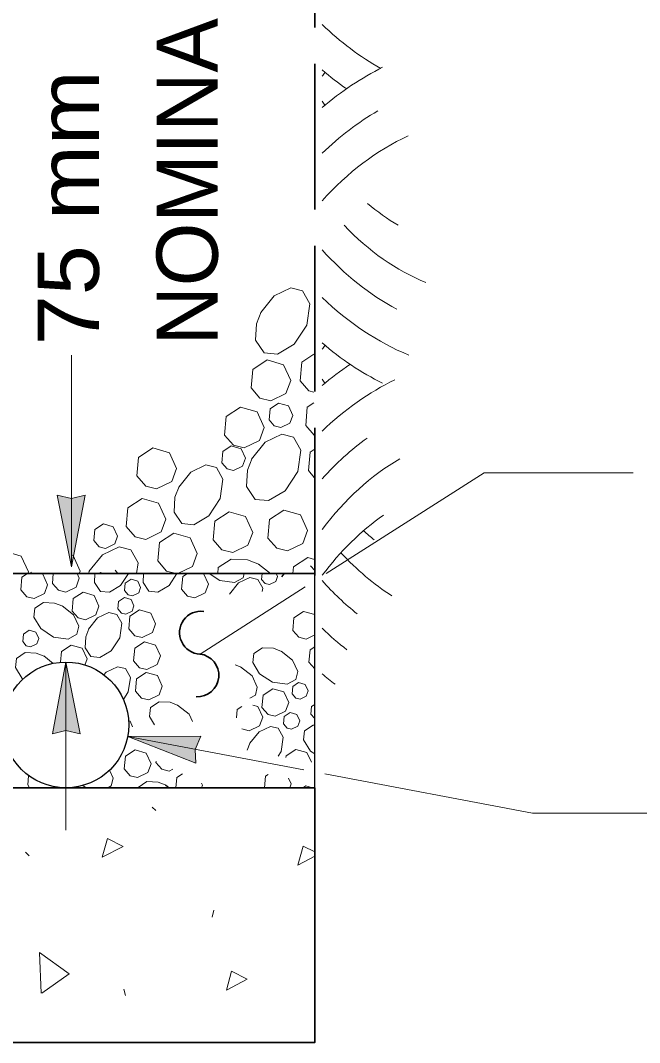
# Model space of a CAD drawing. Extents: x 17672 to 18472, y -9785 to -9267.
# Drawn here: x 18170.6 to 18206.3, y -9679.5 to -9620.6 of the extents above; entities that cross this region are included whole.
import ezdxf

# ---------------------------------------------------------------- set-up
doc = ezdxf.new("R2010")
doc.units = 0
doc.header["$LTSCALE"] = 1.4
doc.linetypes.add('LONG_DASHED', pattern=[7.5, 6, -1.5])
for name, color, linetype, lineweight in [('1', 7, 'Continuous', 13), ('15', 7, 'Continuous', 13), ('16', 7, 'Continuous', 13)]:
    doc.layers.add(name, color=color, linetype=linetype, lineweight=lineweight)
doc.layers.add('19', color=7, linetype='Continuous')

msp = doc.modelspace()

# ---------------------------------------------------------------- hatches: boundary and pattern name
at = {"layer": '16'}
for points in [[(18173.572, -9652.079), (18174.354, -9647.942), (18173.572, -9648.128), (18172.751, -9647.942)], [(18173.246, -9657.572), (18172.465, -9661.709), (18173.246, -9661.523), (18174.067, -9661.709)], [(18176.808, -9661.873), (18180.727, -9663.413), (18180.69, -9662.609), (18181.026, -9661.839)]]:
    msp.add_hatch(color=256, dxfattribs=at).paths.add_polyline_path(points)

# ---------------------------------------------------------------- linework, layer by layer
at = {"layer": '1', "linetype": 'LONG_DASHED', "lineweight": 35}
msp.add_line((18187.59, -9652.464), (18187.59, -9595.62), dxfattribs=at)
at = {"layer": '1'}
for p, q in [((18187.553, -9644.488), (18187.068, -9643.931)), ((18187.564, -9646.918), (18187.224, -9646.526)), ((18184.356, -9651.92), (18185.043, -9652.464)), ((18187.59, -9652.291), (18187.347, -9652.012)), ((18171.284, -9652.464), (18171.221, -9652.392)), ((18172.472, -9653.03), (18172.521, -9652.464)), ((18174.539, -9652.464), (18174.602, -9652.303)), ((18176.249, -9652.464), (18176.079, -9652.269)), ((18184.526, -9652.802), (18184.555, -9652.464)), ((18187.585, -9652.464), (18187.568, -9652.584)), ((18171.965, -9657.221), (18172.506, -9657.648)), ((18182.999, -9657.729), (18183.347, -9657.866)), ((18187.59, -9657.964), (18187.259, -9657.584)), ((18183.7, -9662.655), (18183.874, -9662.212)), ((18178.435, -9663.361), (18178.442, -9663.288)), ((18174.423, -9664.822), (18174.222, -9664.69)), ((18178.224, -9665.937), (18178.433, -9666.138)), ((18170.923, -9668.535), (18171.134, -9668.751)), ((18187.59, -9668.773), (18186.621, -9669.285)), ((18181.678, -9672.285), (18181.766, -9671.891)), ((18176.577, -9676.449), (18176.688, -9676.81))]:
    msp.add_line(p, q, dxfattribs=at)
at = {"layer": '1', "lineweight": 25}
for p, q in [((18185.693, -9652.658), (18185.847, -9652.464)), ((18187.59, -9664.822), (18187.59, -9652.569)), ((18178.992, -9664.663), (18179.193, -9664.822))]:
    msp.add_line(p, q, dxfattribs=at)
at = {"layer": '1'}
for points in [[(18184.475, -9637.412), (18185.247, -9636.438), (18186.212, -9635.986), (18186.889, -9636.149), (18187.306, -9636.904), (18187.132, -9638.134), (18186.403, -9639.239), (18185.447, -9639.814), (18184.68, -9639.741), (18184.184, -9639.002), (18184.228, -9638.058), (18184.5, -9637.363)], [(18186.743, -9641.342), (18186.839, -9640.272), (18187.532, -9639.816)], [(18187.542, -9642.001), (18187.254, -9641.929), (18186.744, -9641.342)], [(18184.954, -9643.598), (18185.012, -9642.956), (18185.507, -9642.631), (18186.077, -9642.795), (18186.324, -9643.342), (18186.16, -9643.788), (18185.632, -9644.045), (18185.261, -9643.951), (18184.955, -9643.599)], [(18187.068, -9643.931), (18187.163, -9642.861), (18187.545, -9642.61)], [(18183.953, -9645.859), (18184.725, -9644.884), (18185.691, -9644.433), (18186.368, -9644.596), (18186.785, -9645.35), (18186.611, -9646.581), (18185.882, -9647.685), (18184.925, -9648.26), (18184.158, -9648.187), (18183.663, -9647.448), (18183.706, -9646.505), (18183.979, -9645.81)], [(18182.228, -9646.073), (18182.286, -9645.431), (18182.782, -9645.106), (18183.351, -9645.27), (18183.599, -9645.817), (18183.434, -9646.263), (18182.907, -9646.519), (18182.535, -9646.425), (18182.229, -9646.073)], [(18177.344, -9646.832), (18177.439, -9645.762), (18178.266, -9645.219), (18179.215, -9645.493), (18179.627, -9646.405), (18179.353, -9647.149), (18178.474, -9647.575), (18177.855, -9647.419), (18177.344, -9646.831)], [(18187.223, -9646.526), (18187.319, -9645.456), (18187.557, -9645.3)], [(18179.752, -9647.486), (18180.447, -9646.609), (18181.316, -9646.202), (18181.924, -9646.349), (18182.3, -9647.028), (18182.144, -9648.136), (18181.488, -9649.13), (18180.626, -9649.647), (18179.937, -9649.582), (18179.49, -9648.916), (18179.53, -9648.067), (18179.775, -9647.442)], [(18178.538, -9651.74), (18178.633, -9650.669), (18179.46, -9650.128), (18180.409, -9650.401), (18180.821, -9651.313), (18180.547, -9652.057), (18179.707, -9652.464)], [(18174.576, -9652.352), (18175.348, -9651.377), (18176.314, -9650.925), (18176.991, -9651.089), (18177.407, -9651.843), (18177.32, -9652.464)], [(18168.828, -9652.464), (18168.894, -9651.723), (18169.72, -9651.181), (18170.67, -9651.454), (18171.082, -9652.366), (18171.046, -9652.464)], [(18173.56, -9651.387), (18173.656, -9651.415), (18174.068, -9652.328), (18174.018, -9652.464)], [(18181.995, -9652.464), (18182.027, -9652.124), (18182.767, -9651.629), (18183.71, -9651.672), (18184.405, -9651.945)], [(18186.332, -9652.464), (18186.367, -9652.077), (18187.193, -9651.535), (18187.586, -9651.648)], [(18179.594, -9652.464), (18179.049, -9652.327), (18178.538, -9651.74)], [(18170.648, -9653.403), (18170.712, -9652.68), (18171.04, -9652.464)], [(18171.795, -9652.464), (18171.913, -9652.496), (18172.19, -9653.113), (18172.006, -9653.616), (18171.411, -9653.903), (18170.994, -9653.8), (18170.648, -9653.403)], [(18173.889, -9652.464), (18174.014, -9652.741), (18173.83, -9653.243), (18173.234, -9653.533), (18172.817, -9653.427), (18172.472, -9653.03)], [(18176.854, -9652.464), (18176.398, -9653.153), (18175.751, -9653.54), (18175.234, -9653.493), (18174.898, -9652.991), (18174.923, -9652.464)], [(18175.171, -9652.464), (18175.248, -9652.414), (18175.423, -9652.464)], [(18179.648, -9652.464), (18179.195, -9653.148), (18178.55, -9653.538), (18178.031, -9653.488), (18177.695, -9652.988), (18177.719, -9652.464)], [(18179.913, -9653.366), (18179.977, -9652.643), (18180.251, -9652.464)], [(18181.178, -9652.464), (18181.457, -9653.079), (18181.271, -9653.582), (18180.678, -9653.868), (18180.259, -9653.763), (18179.913, -9653.366)], [(18183.526, -9652.464), (18183.467, -9652.704), (18182.957, -9652.988), (18182.124, -9652.871), (18181.509, -9652.464)], [(18182.675, -9653.66), (18183.197, -9653.001), (18183.849, -9652.694), (18184.308, -9652.807), (18184.59, -9653.314), (18184.563, -9653.503)], [(18185.376, -9652.464), (18185.452, -9652.631), (18185.342, -9652.932), (18184.984, -9653.104), (18184.734, -9653.042), (18184.526, -9652.802)], [(18173.026, -9654.332), (18173.685, -9654.854), (18173.991, -9655.506), (18173.881, -9655.964), (18173.371, -9656.246), (18172.538, -9656.128), (18171.793, -9655.636), (18171.403, -9654.988), (18171.452, -9654.471), (18171.952, -9654.136), (18172.59, -9654.165), (18173.06, -9654.349)], [(18174.553, -9655.68), (18175.075, -9655.02), (18175.727, -9654.716), (18176.185, -9654.827), (18176.467, -9655.337), (18176.349, -9656.17), (18175.857, -9656.915), (18175.21, -9657.305), (18174.692, -9657.256), (18174.357, -9656.756), (18174.386, -9656.118), (18174.57, -9655.648)], [(18186.327, -9655.741), (18186.394, -9655.015), (18186.952, -9654.65), (18187.59, -9654.834)], [(18187.59, -9656.001), (18187.092, -9656.243), (18186.673, -9656.138), (18186.327, -9655.741)], [(18172.933, -9657.584), (18172.989, -9656.954), (18173.548, -9656.589), (18174.19, -9656.773), (18174.469, -9657.39), (18174.34, -9657.741)], [(18185.648, -9656.937), (18186.308, -9657.459), (18186.614, -9658.114), (18186.501, -9658.569), (18185.994, -9658.851), (18185.161, -9658.734), (18184.413, -9658.241), (18184.026, -9657.594), (18184.075, -9657.077), (18184.575, -9656.741), (18185.212, -9656.77), (18185.683, -9656.954)], [(18187.259, -9657.584), (18187.322, -9656.861), (18187.59, -9656.687)], [(18170.768, -9658.55), (18170.732, -9658.523), (18170.342, -9657.878), (18170.391, -9657.359), (18170.891, -9657.023), (18171.528, -9657.052), (18171.999, -9657.239)], [(18175.438, -9658.31), (18175.567, -9658.148), (18176.219, -9657.841), (18176.678, -9657.952), (18176.96, -9658.462), (18176.842, -9659.295), (18176.558, -9659.724)], [(18183.315, -9657.849), (18183.974, -9658.371), (18184.278, -9659.023), (18184.168, -9659.481), (18183.852, -9659.655)], [(18178.352, -9661.192), (18178.065, -9660.714), (18178.114, -9660.197), (18178.614, -9659.861), (18179.251, -9659.89), (18179.722, -9660.074)], [(18179.688, -9660.057), (18180.347, -9660.579), (18180.545, -9661.001)], [(18183.072, -9660.783), (18183.114, -9660.312), (18183.384, -9660.136)], [(18184.028, -9660.05), (18184.315, -9660.131), (18184.595, -9660.748), (18184.408, -9661.251), (18183.815, -9661.538), (18183.396, -9661.432), (18183.391, -9661.427)], [(18187.367, -9660.572), (18187.406, -9660.138), (18187.59, -9660.018)], [(18176.864, -9660.959), (18176.947, -9660.981), (18177.09, -9661.3)], [(18187.59, -9660.815), (18187.575, -9660.81), (18187.369, -9660.572)], [(18183.857, -9662.246), (18184.379, -9661.587), (18185.031, -9661.28), (18185.489, -9661.391), (18185.771, -9661.9), (18185.653, -9662.734), (18185.482, -9662.993)], [(18187.59, -9662.871), (18187.342, -9662.707), (18186.952, -9662.062), (18187.001, -9661.542), (18187.504, -9661.207), (18187.59, -9661.212)], [(18185.933, -9663.077), (18185.943, -9662.974), (18186.501, -9662.606), (18187.144, -9662.792), (18187.396, -9663.354)], [(18179.413, -9663.758), (18179.2, -9663.864), (18178.781, -9663.758), (18178.435, -9663.361)], [(18175.756, -9663.812), (18175.967, -9664.261), (18175.854, -9664.717), (18175.666, -9664.822)], [(18179.585, -9664.822), (18179.639, -9664.236), (18179.962, -9664.025)], [(18171.146, -9664.822), (18171.045, -9664.653), (18171.092, -9664.133), (18171.107, -9664.123)], [(18177.416, -9664.822), (18177.416, -9664.8), (18177.918, -9664.467), (18178.555, -9664.496), (18179.026, -9664.68)], [(18181.065, -9664.56), (18181.117, -9664.672), (18181.063, -9664.822)], [(18184.697, -9664.822), (18184.756, -9664.163), (18184.913, -9664.06)], [(18186.087, -9664.27), (18186.237, -9664.596), (18186.153, -9664.822)], [(18186.908, -9664.822), (18187.072, -9664.714), (18187.452, -9664.822)], [(18186.621, -9669.285), (18186.918, -9668.19), (18187.59, -9668.523)], [(18171.82, -9676.672), (18171.722, -9674.324), (18173.438, -9675.552), (18171.852, -9676.668)]]:
    msp.add_lwpolyline(points, dxfattribs=at)
for points in [[(18183.922, -9641.758), (18184.017, -9640.688), (18184.844, -9640.145), (18185.793, -9640.418), (18186.205, -9641.331), (18185.931, -9642.075), (18185.052, -9642.5), (18184.433, -9642.344)], [(18182.393, -9644.473), (18182.488, -9643.403), (18183.314, -9642.861), (18184.264, -9643.134), (18184.677, -9644.046), (18184.402, -9644.79), (18183.523, -9645.216), (18182.904, -9645.06)], [(18176.719, -9649.751), (18176.814, -9648.681), (18177.64, -9648.139), (18178.589, -9648.412), (18179.002, -9649.325), (18178.728, -9650.068), (18177.849, -9650.495), (18177.23, -9650.339)], [(18181.733, -9650.517), (18181.828, -9649.447), (18182.654, -9648.905), (18183.603, -9649.178), (18184.016, -9650.09), (18183.742, -9650.834), (18182.863, -9651.26), (18182.244, -9651.104)], [(18184.895, -9650.417), (18184.99, -9649.347), (18185.816, -9648.805), (18186.766, -9649.078), (18187.178, -9649.99), (18186.904, -9650.734), (18186.025, -9651.16), (18185.406, -9651.004)], [(18174.851, -9650.567), (18174.908, -9649.925), (18175.404, -9649.599), (18175.974, -9649.763), (18176.221, -9650.311), (18176.057, -9650.757), (18175.529, -9651.013), (18175.158, -9650.919)], [(18176.629, -9653.449), (18176.668, -9653.015), (18177.004, -9652.795), (18177.389, -9652.908), (18177.555, -9653.275), (18177.445, -9653.579), (18177.087, -9653.751), (18176.837, -9653.687)], [(18173.609, -9654.631), (18173.673, -9653.908), (18174.232, -9653.54), (18174.874, -9653.724), (18175.153, -9654.341), (18174.967, -9654.844), (18174.374, -9655.133), (18173.955, -9655.028)], [(18176.244, -9654.508), (18176.283, -9654.074), (18176.619, -9653.854), (18177.004, -9653.964), (18177.17, -9654.334), (18177.06, -9654.638), (18176.702, -9654.81), (18176.452, -9654.746)], [(18176.874, -9655.653), (18176.938, -9654.93), (18177.496, -9654.562), (18178.139, -9654.748), (18178.418, -9655.363), (18178.232, -9655.866), (18177.639, -9656.155), (18177.219, -9656.05)], [(18170.756, -9656.388), (18170.795, -9655.954), (18171.131, -9655.734), (18171.516, -9655.844), (18171.683, -9656.214), (18171.572, -9656.515), (18171.214, -9656.689), (18170.964, -9656.626)], [(18177.151, -9657.503), (18177.215, -9656.778), (18177.773, -9656.413), (18178.416, -9656.596), (18178.695, -9657.214), (18178.509, -9657.716), (18177.916, -9658.006), (18177.496, -9657.898)], [(18177.256, -9659.256), (18177.32, -9658.533), (18177.879, -9658.167), (18178.521, -9658.351), (18178.8, -9658.969), (18178.614, -9659.471), (18178.018, -9659.758), (18177.602, -9659.653)], [(18184.55, -9660.199), (18184.617, -9659.476), (18185.173, -9659.109), (18185.815, -9659.295), (18186.095, -9659.91), (18185.908, -9660.413), (18185.315, -9660.702), (18184.896, -9660.596)], [(18186.288, -9659.408), (18186.327, -9658.974), (18186.663, -9658.753), (18187.048, -9658.864), (18187.215, -9659.234), (18187.104, -9659.535), (18186.746, -9659.709), (18186.496, -9659.645)], [(18185.795, -9661.141), (18185.835, -9660.707), (18186.17, -9660.486), (18186.555, -9660.596), (18186.722, -9660.966), (18186.612, -9661.268), (18186.254, -9661.442), (18186.004, -9661.378)], [(18176.612, -9663.734), (18176.675, -9663.008), (18177.234, -9662.643), (18177.876, -9662.827), (18178.156, -9663.444), (18177.969, -9663.947), (18177.376, -9664.234), (18176.957, -9664.131)], [(18175.327, -9668.832), (18175.641, -9667.751), (18176.543, -9668.207)], [(18182.499, -9676.494), (18182.795, -9675.4), (18183.697, -9675.856)]]:
    msp.add_lwpolyline(points, close=True, dxfattribs=at)
at = {"layer": '1', "lineweight": 35}
msp.add_lwpolyline([(18187.59, -9652.569), (18187.59, -9652.464), (18157.665, -9652.464), (18158.903, -9664.822), (18187.59, -9664.822)], dxfattribs=at)
msp.add_lwpolyline([(18134.457, -9664.822), (18095.729, -9664.822), (18095.729, -9679.521), (18187.59, -9679.521), (18187.59, -9664.822), (18158.903, -9664.822)], close=True, dxfattribs=at)
at = {"layer": '1', "lineweight": 25}
msp.add_lwpolyline([(18158.903, -9664.822), (18187.59, -9664.822), (18158.903, -9664.822)], dxfattribs=at)
msp.add_circle((18173.246, -9661.196), 3.626, dxfattribs=at)
at = {"layer": '1'}
for centre, major_axis, start_param, end_param in [((18198.022, -9600.657), (0, -24.471), 5.678359, 5.89692), ((18198.022, -9648.347), (0, 26.675), 0.346641, 0.54876), ((18198.022, -9600.657), (0, -26.675), 5.734425, 5.819072), ((18174.27, -9602.676), (0, -28.469), 0.735703, 0.74718), ((18174.27, -9646.329), (0, 28.469), 5.536005, 5.547483), ((18198.022, -9648.347), (0, 24.471), 0.396562, 0.604826), ((18198.022, -9648.347), (0, 22.266), 0.321019, 0.675019), ((18198.092, -9613.94), (0, -20.062), 5.740022, 5.87774), ((18198.022, -9616.405), (0, -20.062), 5.633205, 5.999911), ((18198.022, -9616.405), (0, -22.266), 5.608166, 5.918958), ((18198.022, -9616.405), (0, -24.471), 5.678359, 5.994746), ((18198.022, -9616.405), (0, -26.675), 5.734425, 5.935901), ((18174.27, -9618.423), (0, -28.469), 0.735703, 0.74718), ((18198.022, -9664.382), (0, 26.675), 0.453104, 0.54876), ((18174.27, -9662.363), (0, 28.469), 5.536005, 5.547483), ((18198.022, -9664.382), (0, 24.471), 0.336904, 0.604826), ((18198.022, -9664.382), (0, 22.266), 0.481461, 0.675019), ((18198.022, -9664.382), (0, 20.062), 0.393014, 0.765516), ((18198.022, -9667.033), (0, 20.062), 0.464937, 0.765516), ((18198.092, -9633.027), (0, -20.062), 5.720851, 5.771052), ((18198.022, -9635.491), (0, -20.062), 5.616853, 5.85583), ((18198.022, -9635.491), (0, -22.266), 5.608166, 5.761688), ((18198.022, -9635.491), (0, -24.471), 5.678359, 5.774233), ((18198.022, -9635.491), (0, -26.675), 5.734425, 5.779681)]:
    msp.add_ellipse(centre, major_axis=major_axis, ratio=0.719298, start_param=start_param, end_param=end_param, dxfattribs=at)
at = {"layer": '15'}
for p, q in [((18173.572, -9652.079), (18173.572, -9639.863)), ((18188.244, -9652.469), (18197.359, -9646.648)), ((18197.359, -9646.648), (18205.943, -9646.648)), ((18180.977, -9657.111), (18187.036, -9653.241)), ((18173.246, -9657.572), (18173.246, -9667.268)), ((18176.808, -9661.873), (18186.965, -9663.797)), ((18188.163, -9664.025), (18200.136, -9666.295)), ((18200.136, -9666.295), (18207.585, -9666.295))]:
    msp.add_line(p, q, dxfattribs=at)
at = {"layer": '16'}
for points in [[(18173.572, -9652.079), (18174.354, -9647.942), (18173.572, -9648.128), (18172.751, -9647.942)], [(18173.246, -9657.572), (18172.465, -9661.709), (18173.246, -9661.523), (18174.067, -9661.709)], [(18176.808, -9661.873), (18180.727, -9663.413), (18180.69, -9662.609), (18181.026, -9661.839)]]:
    msp.add_lwpolyline(points, close=True, dxfattribs=at)
at = {"layer": '16', "lineweight": 35}
for centre, start, end in [((18181.037, -9655.874), 82.84243, 267.15757), ((18180.822, -9658.338), 267.15757, 82.84243)]:
    msp.add_arc(centre, 1.238, start, end, dxfattribs=at)

# ---------------------------------------------------------------- texts
at = {"layer": '19'}
msp.add_text('NOMINAL', height=3.529, rotation=90, dxfattribs=at).set_placement((18181.999, -9639.297))
at = {"layer": '19', "width": 1.1}
msp.add_text('75 mm', height=3.529, rotation=90, dxfattribs=at).set_placement((18175.148, -9639.297))

doc.saveas('drawing.dxf')
